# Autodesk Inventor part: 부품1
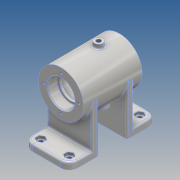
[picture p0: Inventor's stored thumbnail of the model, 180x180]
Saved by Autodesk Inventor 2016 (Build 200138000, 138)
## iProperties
Created: 2017-02
Part Number: 부품1
Material: 알루미늄 6061
Document SubType Name: Modeling
Designer: Administrator
Density: 2.7 g/cm^3
Appearance: 알루미늄 - 평지
Mass: 354.751 g
Surface Area: 422.76 cm^2
Volume: 131.389 cm^3
Author: Administrator
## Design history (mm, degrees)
sketch "스케치1"
  geometry: L1 (0, 0)-(54, 0); L2 (54, 104)-(0, 104); L3 (0, 69)-(54, 69); L4 (0, 35)-(54, 35); L5 (0, 104)-(0, 69); L6 (0, 35)-(0, 0); L7 (54, 0)-(54, 35); L8 (54, 69)-(54, 104)
  constraints: 16 end point, 5 parallel, 2 perpendicular, 1 horizontal
  dimensions: "d0" = 54 distance of L2.end L2.start; "d1" = 104 distance of L2.start L1.end; "d4" = 35 distance between parallel lines of L1 L4; "d5" = 54 distance between parallel lines of L6 L7; "d6" = 69 distance between parallel lines of L3 L1; "d7" = 54 distance between parallel lines of L6 L8
extrude "돌출1" new body sketch "스케치1" distance "d8" = 8; taper "d9" = 0 deg
node "작업 평면1"
sketch "스케치2"
  geometry: L1 (8, -69)-(0, -69) reference; L2 (0, -69)-(0, -34) reference; L3 (0, -34)-(8, -34) reference; L4 (8, -34)-(8, -69) reference; L5 (0, 35)-(8, 35) reference; L6 (8, 35)-(8, 0) reference; L7 (8, 0)-(0, 0) reference; L8 (0, 0)-(0, 35) reference; L9 (0, -69)-(0, -34) reference; L10 (60, 18)-(60, -52); L11 (60, -52)-(87, -52); L12 (87, -52)-(87, 18); L13 (87, 18)-(60, 18)
  constraints: 8 end point, 1 horizontal, 1 perpendicular, 1 vertical
  dimensions: "d11" = 70 distance of L10.start L10.end; "d12" = 27 distance of L10.end L11.end; "d13" = 70 distance of L11.end L12.end; "d14" = 60 distance between parallel lines of L8 L10; "d15" = 52 distance between parallel lines of L7 L11
revolve "회전1" sketch "스케치2" stored, may be unused: angle "d16" = 90 deg
sketch "스케치3"
  geometry: L1 (0, 69)-(54, 69) reference; L2 (54, 104)-(54, 69) reference; L3 (54, 69)-(0, 69) reference; L4 (0, 69)-(0, 104) reference; L5 (0, 104)-(54, 104) reference; L6 (0, 0)-(0, 35) reference; L7 (0, 35)-(54, 35) reference; L8 (54, 35)-(54, 0) reference; L9 (54, 0)-(0, 0) reference; L10 (54, 77)-(0, 77); L11 (0, 104)-(0, 69) reference; L12 (0, 35)-(0, 0) reference; L13 (0, 27)-(54, 27); L14 (54, 0)-(54, 35) reference; L15 (54, 27)-(54, 35); L16 (54, 35)-(0, 35) reference; L17 (54, 35)-(0, 35); L18 (0, 35)-(0, 27); L19 (0, 77)-(0, 69); L20 (0, 69)-(54, 69) reference; L21 (0, 69)-(54, 69); L22 (54, 69)-(54, 77)
  constraints: 16 end point, 4 point on line, 3 collinear, 3 perpendicular, 1 horizontal, 1 vertical
  dimensions: "d17" = 8 distance between parallel lines of L1 L10; "d18" = 8 distance between parallel lines of L7 L13
extrude "돌출2" join sketch "스케치3" stored distance "d19" = 8; taper "d20" = 0 deg
node "작업 평면2"
sketch "스케치4"
  geometry: L1 (0, 35)-(8, 35) reference; L2 (8, 35)-(8, 8) reference; L3 (8, 8)-(33, 8) reference; L4 (33, 8)-(33, 18) reference; L5 (33, 18)-(87, 18) reference; L6 (87, 18)-(87, -52) reference; L7 (87, -52)-(33, -52) reference; L8 (33, -52)-(33, -42) reference; L9 (33, -42)-(8, -42) reference; L10 (8, -42)-(8, -69) reference; L11 (8, -69)-(0, -69) reference; L12 (0, -69)-(0, -34) reference; L13 (0, -34)-(33, -34) reference; L14 (33, -34)-(33, 0) reference; L15 (33, 0)-(0, 0) reference; L16 (0, 0)-(0, 35) reference; L17 (60, 18)-(60, -52); L18 (33, -52)-(87, -52) reference; L19 (60, -52)-(76, -52); L20 (76, -52)-(76, -40); L21 (76, -40)-(74, -40); L22 (74, -40)-(74, -37); L23 (74, -37)-(82, -37); L24 (82, -37)-(82, 3); L25 (82, 3)-(74, 3); L26 (74, 3)-(74, 6); L27 (74, 6)-(76, 6); L28 (76, 6)-(76, 18); L29 (76, 18)-(60, 18); L30 (33, 18)-(87, 18) reference
  constraints: 24 end point, 6 perpendicular, 4 point on line, 2 midpoint, 1 collinear, 1 horizontal
  dimensions: "d21" = 16 distance of L17.end L19.end; "d22" = 12 distance of L19.end L20.end; "d23" = 2 distance of L20.end L21.end; "d24" = 3 distance of L21.end L22.end; "d25" = 8 distance of L22.end L23.end; "d26" = 40 distance of L23.end L24.end; "d27" = 8 distance of L24.end L25.end; "d28" = 3 distance of L25.end L26.end; "d29" = 2 distance of L26.end L27.end
revolve "회전2" sketch "스케치4" stored, may be unused: angle "d30" = 90 deg
node "작업 평면3"
sketch "스케치5"
  geometry: L1 (-54, 87)-(0, 87) reference; L2 (-54, 77)-(-54, 104) reference; C1 r 5 at (-27, 62); 1 further point
  constraints: 1 centre point
  dimensions: "d33" = 10 diameter of C1; "d34" = 25 distance from line of L1 C1.centre; "d35" = 27 distance from line of L2 C1.centre
extrude "돌출3" join sketch "스케치5" stored distance "d36" = 8; taper "d37" = 0 deg
sketch "스케치6"
  geometry: C1 r 5 at (0, 0) reference; 1 further point
hole "구멍1" sketch "스케치6" at (0, 0) diameter "d38" = 5.188; stored, may be unused: countersink angle "d42" = 90 deg, drill point angle "d44" = 118 deg; dims "d39" = 12, "d40" = 4, "d41" = 2, "d43" = 15
sketch "스케치7" dims "d45" = 42
  geometry: C1 r 16 at (0, 0) reference; C2 r 27 at (0, 0) reference; 3 further points
  constraints: 2 vertical alignment, 1 coincident, 2 other
hole "구멍2" sketch "스케치7" at (0, -21) diameter "d46" = 3.242; stored, may be unused: countersink angle "d50" = 90 deg, drill point angle "d52" = 118 deg; dims "d47" = 8, "d48" = 4, "d49" = 2, "d51" = 10
sketch "스케치8" dims "d56" = 42
  geometry: C1 r 16 at (0, 0) reference; C2 r 27 at (0, 0) reference; 3 further points
  constraints: 2 vertical alignment, 1 coincident, 2 other
hole "구멍3" sketch "스케치8" at (0, 21) diameter "d57" = 3.242; stored, may be unused: countersink angle "d61" = 90 deg, drill point angle "d63" = 118 deg; dims "d58" = 8, "d59" = 4, "d60" = 2, "d62" = 10
sketch "스케치9" dims "d67" = 9, "d68" = 9, "d69" = 9, "d70" = 9
  geometry: L1 (54, 77)-(54, 104) reference; L2 (54, 104)-(0, 104) reference; L3 (0, 104)-(0, 77) reference; L4 (0, 77)-(54, 77) reference; L5 (54, 104)-(54, 77) reference; L6 (0, 104)-(54, 104) reference; L7 (0, 77)-(0, 104) reference; L8 (0, 69)-(0, 77) reference; L9 (54, 69)-(0, 69) reference; L10 (54, 77)-(54, 69) reference; L11 (54, 27)-(0, 27) reference; L12 (0, 0)-(0, 27) reference; L13 (54, 0)-(0, 0) reference; L14 (54, 27)-(54, 0) reference; L15 (54, 35)-(54, 27) reference; L16 (0, 35)-(54, 35) reference; L17 (0, 27)-(0, 35) reference; L18 (14.5, 91.402)-(10, 88.804); L19 (10, 88.804)-(5.5, 91.402); L20 (5.5, 91.402)-(5.5, 96.598); L21 (5.5, 96.598)-(10, 99.196); L22 (10, 99.196)-(14.5, 96.598); L23 (14.5, 96.598)-(14.5, 91.402); L24 (48.5, 91.402)-(44, 88.804); L25 (44, 88.804)-(39.5, 91.402); L26 (39.5, 91.402)-(39.5, 96.598); L27 (39.5, 96.598)-(44, 99.196); L28 (44, 99.196)-(48.5, 96.598); L29 (48.5, 96.598)-(48.5, 91.402); L30 (14.5, 7.402)-(10, 4.804); L31 (10, 4.804)-(5.5, 7.402); L32 (5.5, 7.402)-(5.5, 12.598); L33 (5.5, 12.598)-(10, 15.196); L34 (10, 15.196)-(14.5, 12.598); L35 (14.5, 12.598)-(14.5, 7.402); L36 (48.5, 7.402)-(44, 4.804); L37 (44, 4.804)-(39.5, 7.402); L38 (39.5, 7.402)-(39.5, 12.598); L39 (39.5, 12.598)-(44, 15.196); L40 (44, 15.196)-(48.5, 12.598); L41 (48.5, 12.598)-(48.5, 7.402); 12 further points
  constraints: 48 end point, 4 coincident, 4 horizontal alignment, 4 midpoint, 2 point on line, 60 other
  dimensions: "d71" = 10 distance from line of L2 point (10, 94); "d72" = 10 distance from line of L2 point (44, 94); "d73" = 10 distance from line of L13 point (10, 10); "d74" = 10 distance from line of L13 point (44, 10); "d75" = 10 distance from line of L3 point (10, 94); "d76" = 10 distance from line of L1 point (44, 94); "d77" = 10 distance from line of L12 point (10, 10); "d78" = 10 distance from line of L14 point (44, 10); "d79" = 60 deg angle of L3 L21; "d80" = 150 deg angle of L2 L28
extrude "돌출4" cut sketch "스케치9" distance "d81" = 3; taper "d82" = 0 deg
sketch "스케치10"
  geometry: L1 (14.5, 12.598)-(14.5, 7.402) reference; L2 (14.5, 12.598)-(10, 15.196) reference; L3 (10, 15.196)-(5.5, 12.598) reference; L4 (5.5, 12.598)-(5.5, 7.402) reference; L5 (5.5, 7.402)-(10, 4.804) reference; L6 (10, 4.804)-(14.5, 7.402) reference; L7 (14.5, 7.402)-(14.5, 12.598) reference; L8 (14.5, 96.598)-(10, 99.196) reference; L9 (10, 99.196)-(5.5, 96.598) reference; L10 (5.5, 96.598)-(5.5, 91.402) reference; L11 (5.5, 91.402)-(10, 88.804) reference; L12 (10, 88.804)-(14.5, 91.402) reference; L13 (14.5, 91.402)-(14.5, 96.598) reference; L14 (48.5, 96.598)-(44, 99.196) reference; L15 (44, 99.196)-(39.5, 96.598) reference; L16 (39.5, 96.598)-(39.5, 91.402) reference; L17 (39.5, 91.402)-(44, 88.804) reference; L18 (44, 88.804)-(48.5, 91.402) reference; L19 (48.5, 91.402)-(48.5, 96.598) reference; L20 (48.5, 12.598)-(44, 15.196) reference; L21 (44, 15.196)-(39.5, 12.598) reference; L22 (39.5, 12.598)-(39.5, 7.402) reference; L23 (39.5, 7.402)-(44, 4.804) reference; L24 (44, 4.804)-(48.5, 7.402) reference; L25 (48.5, 7.402)-(48.5, 12.598) reference; L26 (0, 0)-(0, 35) reference; L27 (0, 35)-(54, 35) reference; L28 (54, 35)-(54, 0) reference; L29 (54, 0)-(0, 0) reference; L30 (54, 104)-(54, 69) reference; L31 (54, 69)-(0, 69) reference; L32 (0, 69)-(0, 104) reference; L33 (0, 104)-(54, 104) reference; C1 r 2.5 at (10, 10); C2 r 2.5 at (44, 10); C3 r 2.5 at (44, 94); C4 r 2.5 at (10, 94)
  constraints: 4 centre point
  dimensions: "d83" = 5 diameter of C1; "d84" = 5 diameter of C2; "d85" = 5 diameter of C3; "d86" = 5 diameter of C4; "d87" = 4.5 distance from line of L13 C4.centre; "d88" = 5.19615 distance of L8.end C4.centre; "d89" = 4.5 distance from line of L1 C1.centre; "d90" = 5.19615 distance of L2.end C1.centre; "d91" = 4.5 distance from line of L25 C2.centre; "d92" = 5.19615 distance of L20.end C2.centre; "d93" = 4.5 distance from line of L19 C3.centre; "d94" = 5.19615 distance of L14.end C3.centre
extrude "돌출5" cut sketch "스케치10" stored distance "d95" = 3; taper "d96" = 0 deg
node "작업 평면4"
sketch "스케치11"
  geometry: L1 (0, 0)-(27, 0); L2 (0, 0)-(27, 0); L3 (0, 0)-(30, 0); L4 (19.37, -18.81)-(21.371, -21.892); L5 (16.339, -25.16)-(21.371, -21.892); L6 (-27, -60)-(-27, 0) reference; L7 (-27, -60)-(27, -60) reference; L8 (16.339, -25.16)-(14.705, -22.644); C1 r 22 at (0, 0) reference; C2 r 22 at (0, 0) reference; C3 r 27 at (0, 0) reference; C4 r 22 at (0, 0) reference; C5 r 27 at (0, 0) reference; A1 r 27 centre (0, 0) between (14.705, -22.644) and (19.37, -18.81); 1 further point
  constraints: 12 end point, 3 horizontal, 2 point on circle, 1 centre point, 1 coincident, 1 horizontal alignment, 1 point on line, 2 other
  dimensions: "d104" = 30 distance from line of C1.centre L5; "d105" = 6 distance from line of point (0, 0) L4; "d107" = 33 deg angle of L7 L5; "d108" = 33 deg angle of L6 L4; "d109" = 57 deg angle of L7 L8; "d110" = 1.63392 horizontal distance of L5.start L8.end
revolve "회전3" sketch "스케치11" stored, may be unused: angle "d111" = 90 deg
sketch "스케치12"
  geometry: C1 r 6 at (0, 0) reference; 1 further point
hole "구멍4" sketch "스케치12" at (0, 0) diameter "d112" = 5.188; stored, may be unused: countersink angle "d116" = 90 deg, drill point angle "d118" = 118 deg; dims "d113" = 16, "d114" = 4, "d115" = 2, "d117" = 20
fillet "모깎기1" dims "d119" = 2
fillet "모깎기2" dims "d120" = 10
fillet "모깎기3" dims "d121" = 2
fillet "모깎기4" dims "d122" = 2
fillet "모깎기5" dims "d123" = 2
fillet "모깎기6" dims "d124" = 0.3
fillet "모깎기7" dims "d125" = 3
chamfer "모따기1" distance "d126" = 1; stored, may be unused: second distance "d127" = 2, angle "d128" = 45 deg
sketch "스케치13"
  geometry: L1 (-27, 16)-(-27, -54) reference; L2 (27, 16)-(27, -54) reference; L3 (-27, -54)-(27, -54) reference; L4 (-27, 16)-(27, 16) reference; L5 (2.402, -2.408)-(2.402, -35.592); L6 (2.402, -35.592)-(-2.402, -35.592); L7 (-2.402, -35.592)-(-2.402, -2.408); L8 (-2.402, -2.408)-(2.402, -2.408); 1 further point
  constraints: 2 other
feature "엠보싱1" sketch "스케치13" dims "d0" = 54, "d1" = 104, "d4" = 35, "d5" = 54, "d6" = 69, "d7" = 54, "d130" = 0.5, "d131" = 0
fillet "모깎기8" dims "d132" = 2
node "솔리드1"
pattern_circular "원형 패턴1" dims angle "d54" = 360 deg
pattern_circular "원형 패턴2" dims angle "d65" = 360 deg
node "절단 모서리 투영1"
node "절단 모서리 투영2"
node "절단 모서리 투영3"
node "절단 모서리 투영4"
node "절단 모서리 투영5"
node "절단 모서리 투영6"
node "절단 모서리 투영7"
node "절단 모서리 투영8"
other parameters: "d31" = -92, "d100" = 57 deg
